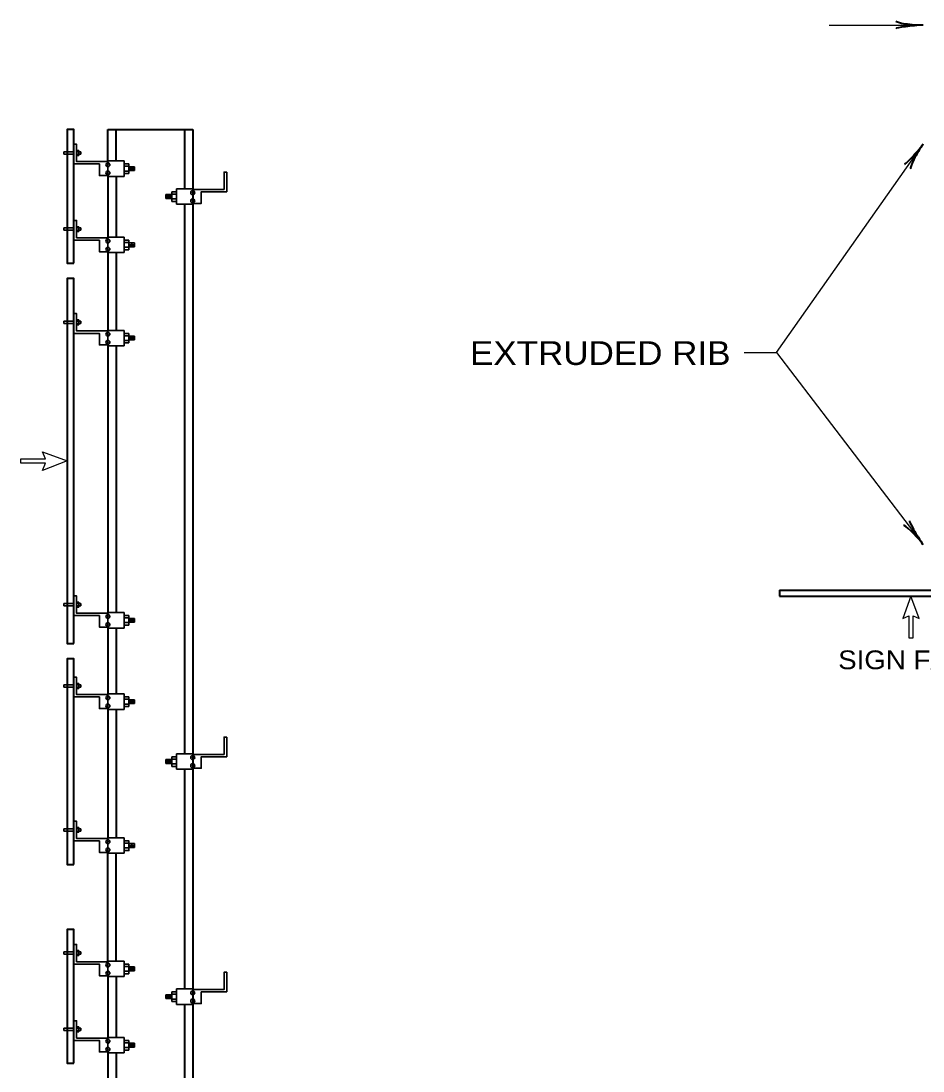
# Model space of a CAD drawing. Extents: x 851 to 1706, y -23 to 521.
# Drawn here: x 1360 to 1475.1, y 110.6 to 244.7 of the extents above; entities that cross this region are included whole.
import ezdxf
from ezdxf.enums import TextEntityAlignment as Align

# ---------------------------------------------------------------- set-up
doc = ezdxf.new("R2010")
doc.units = 0
doc.header["$PDMODE"] = 32
doc.header["$PDSIZE"] = 0.5
doc.layers.add('1', color=7, linetype='Continuous', lineweight=35)

msp = doc.modelspace()

# ---------------------------------------------------------------- linework, layer by layer
at = {"layer": '1', "lineweight": 25}
for p, q in [((1463.149, 244.147), (1475.115, 244.147)), ((1456.404, 202.356), (1475.115, 177.854)), ((1386.238, 153.264), (1385.844, 153.264)), ((1386.238, 153.264), (1386.238, 150.749))]:
    msp.add_line(p, q, dxfattribs=at)
at = {"layer": '1', "lineweight": 40}
for p, q in [((1371.049, 230.821), (1381.875, 230.821)), ((1371.049, 226.802), (1371.049, 230.821)), ((1371.049, 230.821), (1381.875, 230.821)), ((1372.082, 226.802), (1372.082, 230.821)), ((1380.841, 230.821), (1380.841, 223.248)), ((1381.875, 230.821), (1381.875, 128.673)), ((1371.049, 224.834), (1371.049, 217.07)), ((1372.082, 224.834), (1372.082, 217.07)), ((1380.841, 221.28), (1380.841, 151.132)), ((1371.049, 215.102), (1371.049, 205.178)), ((1372.082, 215.102), (1372.082, 205.178)), ((1371.049, 203.21), (1371.049, 169.147)), ((1372.082, 203.21), (1372.082, 169.147)), ((1456.789, 172.002), (1540.733, 172.002)), ((1456.789, 172.002), (1456.789, 171.233)), ((1456.789, 171.233), (1540.733, 171.233)), ((1371.049, 167.179), (1371.049, 158.759)), ((1372.082, 167.179), (1372.082, 158.759)), ((1371.049, 156.791), (1371.049, 140.388)), ((1372.082, 156.791), (1372.082, 140.388)), ((1380.841, 149.163), (1380.841, 128.673)), ((1371.049, 128.673), (1371.049, 138.42)), ((1372.082, 128.673), (1372.082, 138.42)), ((1371.049, 124.654), (1371.049, 128.673)), ((1372.082, 124.654), (1372.082, 128.673)), ((1380.841, 128.673), (1380.841, 121.1)), ((1381.875, 128.673), (1381.875, 21.729)), ((1371.049, 122.686), (1371.049, 114.922)), ((1372.082, 122.686), (1372.082, 114.922)), ((1380.841, 119.132), (1380.841, 48.984)), ((1371.049, 112.954), (1371.049, 103.03)), ((1372.082, 112.954), (1372.082, 103.03))]:
    msp.add_line(p, q, dxfattribs=at)
at = {"layer": '1'}
for p, q in [((1365.425, 227.978), (1365.425, 227.677)), ((1366.686, 227.978), (1365.425, 227.978)), ((1366.686, 228.934), (1366.686, 226.419)), ((1367.342, 228.142), (1367.047, 228.142)), ((1367.604, 227.978), (1367.047, 227.978)), ((1367.342, 228.142), (1367.342, 227.513)), ((1367.604, 227.978), (1367.604, 227.677)), ((1366.686, 227.677), (1365.425, 227.677)), ((1367.604, 227.677), (1367.047, 227.677)), ((1367.342, 227.513), (1367.047, 227.513)), ((1371.049, 226.802), (1373.116, 226.802)), ((1371.049, 226.119), (1371.049, 226.802)), ((1373.116, 226.802), (1373.116, 224.834)), ((1371.049, 226.119), (1371.049, 225.517)), ((1371.049, 225.08), (1371.049, 225.517)), ((1373.116, 226.419), (1373.726, 226.419)), ((1373.116, 226.119), (1373.726, 226.119)), ((1373.116, 225.517), (1373.726, 225.517)), ((1373.116, 225.189), (1373.726, 225.189)), ((1373.726, 226.419), (1373.726, 225.189)), ((1373.726, 226.064), (1374.461, 226.064)), ((1373.726, 225.572), (1374.461, 225.572)), ((1373.918, 225.927), (1373.918, 225.681)), ((1374.097, 226.064), (1374.097, 225.572)), ((1374.297, 225.927), (1374.297, 225.681)), ((1374.461, 226.064), (1374.461, 225.572)), ((1386.238, 225.381), (1386.238, 222.865)), ((1371.049, 225.08), (1371.049, 224.834)), ((1371.049, 224.834), (1373.116, 224.834)), ((1379.197, 222.51), (1378.463, 222.51)), ((1378.463, 222.51), (1378.463, 222.018)), ((1378.827, 222.51), (1378.827, 222.018)), ((1379.808, 222.865), (1379.197, 222.865)), ((1379.197, 222.865), (1379.197, 221.635)), ((1379.808, 222.565), (1379.197, 222.565)), ((1381.875, 223.248), (1379.808, 223.248)), ((1379.808, 223.248), (1379.808, 221.28)), ((1381.875, 222.565), (1381.875, 223.248)), ((1381.875, 222.565), (1381.875, 221.963)), ((1379.197, 222.018), (1378.463, 222.018)), ((1378.627, 222.373), (1378.627, 222.127)), ((1379.005, 222.373), (1379.005, 222.127)), ((1379.808, 221.963), (1379.197, 221.963)), ((1379.808, 221.635), (1379.197, 221.635)), ((1381.875, 221.28), (1379.808, 221.28)), ((1381.875, 221.526), (1381.875, 221.963)), ((1381.875, 221.526), (1381.875, 221.28)), ((1366.686, 219.202), (1366.686, 216.687)), ((1365.425, 218.245), (1365.425, 217.945)), ((1366.686, 218.245), (1365.425, 218.245)), ((1366.686, 217.945), (1365.425, 217.945)), ((1367.342, 218.41), (1367.047, 218.41)), ((1367.604, 218.245), (1367.047, 218.245)), ((1367.604, 217.945), (1367.047, 217.945)), ((1367.342, 217.781), (1367.047, 217.781)), ((1367.342, 218.41), (1367.342, 217.781)), ((1367.604, 218.245), (1367.604, 217.945)), ((1371.049, 217.07), (1373.116, 217.07)), ((1371.049, 216.387), (1371.049, 217.07)), ((1371.049, 216.387), (1371.049, 215.785)), ((1373.116, 217.07), (1373.116, 215.102)), ((1373.116, 216.687), (1373.726, 216.687)), ((1373.116, 216.387), (1373.726, 216.387)), ((1373.726, 216.687), (1373.726, 215.457)), ((1373.726, 216.332), (1374.461, 216.332)), ((1373.726, 215.84), (1374.461, 215.84)), ((1373.918, 216.195), (1373.918, 215.949)), ((1374.097, 216.332), (1374.097, 215.84)), ((1374.297, 216.195), (1374.297, 215.949)), ((1374.461, 216.332), (1374.461, 215.84)), ((1371.049, 215.348), (1371.049, 215.785)), ((1371.049, 215.348), (1371.049, 215.102)), ((1371.049, 215.102), (1373.116, 215.102)), ((1373.116, 215.785), (1373.726, 215.785)), ((1373.116, 215.457), (1373.726, 215.457)), ((1366.686, 207.31), (1366.686, 204.795)), ((1367.342, 206.518), (1367.047, 206.518)), ((1367.342, 206.518), (1367.342, 205.889)), ((1365.425, 206.354), (1365.425, 206.053)), ((1366.686, 206.354), (1365.425, 206.354)), ((1366.686, 206.053), (1365.425, 206.053)), ((1367.604, 206.354), (1367.047, 206.354)), ((1367.604, 206.053), (1367.047, 206.053)), ((1367.342, 205.889), (1367.047, 205.889)), ((1367.604, 206.354), (1367.604, 206.053)), ((1371.049, 205.178), (1373.116, 205.178)), ((1371.049, 204.495), (1371.049, 205.178)), ((1373.116, 205.178), (1373.116, 203.21)), ((1371.049, 204.495), (1371.049, 203.893)), ((1371.049, 203.456), (1371.049, 203.893)), ((1373.116, 204.795), (1373.726, 204.795)), ((1373.116, 204.495), (1373.726, 204.495)), ((1373.116, 203.893), (1373.726, 203.893)), ((1373.726, 204.795), (1373.726, 203.565)), ((1373.726, 204.44), (1374.461, 204.44)), ((1373.726, 203.948), (1374.461, 203.948)), ((1373.918, 204.303), (1373.918, 204.057)), ((1374.097, 204.44), (1374.097, 203.948)), ((1374.297, 204.303), (1374.297, 204.057)), ((1374.461, 204.44), (1374.461, 203.948)), ((1371.049, 203.456), (1371.049, 203.21)), ((1371.049, 203.21), (1373.116, 203.21)), ((1373.116, 203.565), (1373.726, 203.565)), ((1365.425, 170.323), (1365.425, 170.022)), ((1366.686, 170.323), (1365.425, 170.323)), ((1366.686, 171.28), (1366.686, 168.765)), ((1367.342, 170.487), (1367.047, 170.487)), ((1367.604, 170.323), (1367.047, 170.323)), ((1367.342, 170.487), (1367.342, 169.858)), ((1367.604, 170.323), (1367.604, 170.022)), ((1366.686, 170.022), (1365.425, 170.022)), ((1367.604, 170.022), (1367.047, 170.022)), ((1367.342, 169.858), (1367.047, 169.858)), ((1371.049, 169.147), (1373.116, 169.147)), ((1371.049, 168.464), (1371.049, 169.147)), ((1373.116, 169.147), (1373.116, 167.179)), ((1371.049, 168.464), (1371.049, 167.863)), ((1371.049, 167.425), (1371.049, 167.863)), ((1373.116, 168.765), (1373.726, 168.765)), ((1373.116, 168.464), (1373.726, 168.464)), ((1373.116, 167.863), (1373.726, 167.863)), ((1373.726, 168.765), (1373.726, 167.534)), ((1373.726, 168.409), (1374.461, 168.409)), ((1373.726, 167.917), (1374.461, 167.917)), ((1373.918, 168.273), (1373.918, 168.026)), ((1374.097, 168.409), (1374.097, 167.917)), ((1374.297, 168.273), (1374.297, 168.026)), ((1374.461, 168.409), (1374.461, 167.917)), ((1371.049, 167.425), (1371.049, 167.179)), ((1371.049, 167.179), (1373.116, 167.179)), ((1373.116, 167.534), (1373.726, 167.534)), ((1366.686, 160.891), (1366.686, 158.376)), ((1365.425, 159.935), (1365.425, 159.634)), ((1366.686, 159.935), (1365.425, 159.935)), ((1366.686, 159.634), (1365.425, 159.634)), ((1367.342, 160.099), (1367.047, 160.099)), ((1367.604, 159.935), (1367.047, 159.935)), ((1367.604, 159.634), (1367.047, 159.634)), ((1367.342, 160.099), (1367.342, 159.47)), ((1367.604, 159.935), (1367.604, 159.634)), ((1367.342, 159.47), (1367.047, 159.47)), ((1371.049, 158.759), (1373.116, 158.759)), ((1371.049, 158.076), (1371.049, 158.759)), ((1373.116, 158.759), (1373.116, 156.791)), ((1373.116, 158.376), (1373.726, 158.376)), ((1373.726, 158.376), (1373.726, 157.146)), ((1371.049, 158.076), (1371.049, 157.474)), ((1371.049, 157.037), (1371.049, 157.474)), ((1371.049, 157.037), (1371.049, 156.791)), ((1373.116, 158.076), (1373.726, 158.076)), ((1373.116, 157.474), (1373.726, 157.474)), ((1373.116, 157.146), (1373.726, 157.146)), ((1373.726, 158.021), (1374.461, 158.021)), ((1373.726, 157.529), (1374.461, 157.529)), ((1373.918, 157.884), (1373.918, 157.638)), ((1374.097, 158.021), (1374.097, 157.529)), ((1374.297, 157.884), (1374.297, 157.638)), ((1374.461, 158.021), (1374.461, 157.529)), ((1371.049, 156.791), (1373.116, 156.791)), ((1386.238, 153.264), (1386.238, 150.749)), ((1379.197, 150.394), (1378.463, 150.394)), ((1378.463, 150.394), (1378.463, 149.902)), ((1378.627, 150.257), (1378.627, 150.011)), ((1378.827, 150.394), (1378.827, 149.902)), ((1379.005, 150.257), (1379.005, 150.011)), ((1379.808, 150.749), (1379.197, 150.749)), ((1379.197, 150.749), (1379.197, 149.519)), ((1379.808, 150.448), (1379.197, 150.448)), ((1381.875, 151.132), (1379.808, 151.132)), ((1379.808, 151.132), (1379.808, 149.163)), ((1381.875, 150.448), (1381.875, 151.132)), ((1381.875, 150.448), (1381.875, 149.847)), ((1379.197, 149.902), (1378.463, 149.902)), ((1379.808, 149.847), (1379.197, 149.847)), ((1379.808, 149.519), (1379.197, 149.519)), ((1381.875, 149.163), (1379.808, 149.163)), ((1381.875, 149.41), (1381.875, 149.847)), ((1381.875, 149.41), (1381.875, 149.163)), ((1366.686, 142.52), (1366.686, 140.006)), ((1365.425, 141.564), (1365.425, 141.263)), ((1366.686, 141.564), (1365.425, 141.564)), ((1366.686, 141.263), (1365.425, 141.263)), ((1367.342, 141.728), (1367.047, 141.728)), ((1367.604, 141.564), (1367.047, 141.564)), ((1367.604, 141.263), (1367.047, 141.263)), ((1367.342, 141.099), (1367.047, 141.099)), ((1367.342, 141.728), (1367.342, 141.099)), ((1367.604, 141.564), (1367.604, 141.263)), ((1371.049, 140.388), (1373.116, 140.388)), ((1371.049, 139.705), (1371.049, 140.388)), ((1371.049, 139.705), (1371.049, 139.103)), ((1373.116, 140.388), (1373.116, 138.42)), ((1373.116, 139.705), (1373.726, 139.705)), ((1373.726, 139.65), (1374.461, 139.65)), ((1373.918, 139.513), (1373.918, 139.267)), ((1374.097, 139.65), (1374.097, 139.158)), ((1374.297, 139.513), (1374.297, 139.267)), ((1374.461, 139.65), (1374.461, 139.158)), ((1371.049, 138.666), (1371.049, 139.103)), ((1371.049, 138.666), (1371.049, 138.42)), ((1371.049, 138.42), (1373.116, 138.42)), ((1373.116, 139.103), (1373.726, 139.103)), ((1373.726, 139.158), (1374.461, 139.158)), ((1366.686, 126.787), (1366.686, 124.272)), ((1367.342, 125.994), (1367.047, 125.994)), ((1367.342, 125.994), (1367.342, 125.365)), ((1365.425, 125.83), (1365.425, 125.529)), ((1366.686, 125.83), (1365.425, 125.83)), ((1366.686, 125.529), (1365.425, 125.529)), ((1367.604, 125.83), (1367.047, 125.83)), ((1367.604, 125.529), (1367.047, 125.529)), ((1367.342, 125.365), (1367.047, 125.365)), ((1367.604, 125.83), (1367.604, 125.529)), ((1371.049, 124.654), (1373.116, 124.654)), ((1371.049, 123.971), (1371.049, 124.654)), ((1373.116, 124.654), (1373.116, 122.686)), ((1371.049, 123.971), (1371.049, 123.37)), ((1371.049, 122.932), (1371.049, 123.37)), ((1373.116, 124.272), (1373.726, 124.272)), ((1373.116, 123.971), (1373.726, 123.971)), ((1373.116, 123.37), (1373.726, 123.37)), ((1373.726, 124.272), (1373.726, 123.041)), ((1373.726, 123.916), (1374.461, 123.916)), ((1373.726, 123.424), (1374.461, 123.424)), ((1373.918, 123.78), (1373.918, 123.534)), ((1374.097, 123.916), (1374.097, 123.424)), ((1374.297, 123.78), (1374.297, 123.534)), ((1374.461, 123.916), (1374.461, 123.424)), ((1371.049, 122.932), (1371.049, 122.686)), ((1371.049, 122.686), (1373.116, 122.686)), ((1373.116, 123.041), (1373.726, 123.041)), ((1386.238, 123.233), (1386.238, 120.718)), ((1379.808, 120.718), (1379.197, 120.718)), ((1379.197, 120.718), (1379.197, 119.488)), ((1381.875, 121.101), (1379.808, 121.101)), ((1379.808, 121.101), (1379.808, 119.132)), ((1381.875, 120.417), (1381.875, 121.101)), ((1379.197, 120.362), (1378.463, 120.362)), ((1378.463, 120.362), (1378.463, 119.87)), ((1379.197, 119.87), (1378.463, 119.87)), ((1378.627, 120.226), (1378.627, 119.98)), ((1378.827, 120.362), (1378.827, 119.87)), ((1379.005, 120.226), (1379.005, 119.98)), ((1379.808, 120.417), (1379.197, 120.417)), ((1379.808, 119.816), (1379.197, 119.816)), ((1379.808, 119.488), (1379.197, 119.488)), ((1381.875, 120.417), (1381.875, 119.816)), ((1381.875, 119.378), (1381.875, 119.816)), ((1381.875, 119.378), (1381.875, 119.132)), ((1381.875, 119.132), (1379.808, 119.132)), ((1366.686, 117.055), (1366.686, 114.54)), ((1365.425, 116.098), (1365.425, 115.797)), ((1366.686, 116.098), (1365.425, 116.098)), ((1366.686, 115.797), (1365.425, 115.797)), ((1367.342, 116.262), (1367.047, 116.262)), ((1367.604, 116.098), (1367.047, 116.098)), ((1367.604, 115.797), (1367.047, 115.797)), ((1367.342, 115.633), (1367.047, 115.633)), ((1367.342, 116.262), (1367.342, 115.633)), ((1367.604, 116.098), (1367.604, 115.797)), ((1371.049, 114.922), (1373.116, 114.922)), ((1371.049, 114.239), (1371.049, 114.922)), ((1371.049, 114.239), (1371.049, 113.637)), ((1373.116, 114.922), (1373.116, 112.954)), ((1373.116, 114.54), (1373.726, 114.54)), ((1373.116, 114.239), (1373.726, 114.239)), ((1373.726, 114.54), (1373.726, 113.309)), ((1373.726, 114.184), (1374.461, 114.184)), ((1373.918, 114.047), (1373.918, 113.801)), ((1374.097, 114.184), (1374.097, 113.692)), ((1374.297, 114.047), (1374.297, 113.801)), ((1374.461, 114.184), (1374.461, 113.692)), ((1371.049, 113.2), (1371.049, 113.637)), ((1371.049, 113.2), (1371.049, 112.954)), ((1371.049, 112.954), (1373.116, 112.954)), ((1373.116, 113.637), (1373.726, 113.637)), ((1373.116, 113.309), (1373.726, 113.309)), ((1373.726, 113.692), (1374.461, 113.692))]:
    msp.add_line(p, q, dxfattribs=at)
at = {"layer": '1', "lineweight": 40}
for points in [[(1366.686, 213.762), (1366.686, 230.821), (1365.856, 230.821), (1365.856, 213.762)], [(1366.686, 165.211), (1366.686, 211.794), (1365.856, 211.794), (1365.856, 165.211)], [(1366.686, 136.998), (1366.686, 163.242), (1365.856, 163.242), (1365.856, 136.998)], [(1366.686, 111.614), (1366.686, 128.673), (1365.856, 128.673), (1365.856, 111.614)]]:
    msp.add_lwpolyline(points, close=True, dxfattribs=at)
at = {"layer": '1', "lineweight": 25}
for points in [[(1366.686, 228.934), (1367.047, 228.934), (1367.047, 226.72)], [(1452.266, 202.356), (1456.404, 202.356), (1475.115, 228.93)], [(1366.686, 219.202), (1367.047, 219.202), (1367.047, 216.988)], [(1366.686, 207.31), (1367.047, 207.31), (1367.047, 205.096)], [(1366.686, 171.28), (1367.047, 171.28), (1367.047, 169.065)], [(1366.686, 160.891), (1367.047, 160.891), (1367.047, 158.677)], [(1366.686, 160.891), (1367.047, 160.891), (1367.047, 158.677)], [(1366.686, 142.52), (1367.047, 142.52), (1367.047, 140.306)], [(1366.686, 126.787), (1367.047, 126.787), (1367.047, 124.572)], [(1366.686, 117.055), (1367.047, 117.055), (1367.047, 114.84)]]:
    msp.add_lwpolyline(points, dxfattribs=at)
at = {"layer": '1'}
for points in [[(1366.686, 228.934), (1367.047, 228.934), (1367.047, 226.72), (1371.049, 226.72)], [(1371.049, 224.943), (1369.966, 224.943), (1369.966, 226.419), (1366.686, 226.419)], [(1386.238, 225.381), (1385.877, 225.381), (1385.877, 223.166), (1381.875, 223.166)], [(1381.875, 221.389), (1382.957, 221.389), (1382.957, 222.865), (1386.238, 222.865)], [(1366.686, 219.202), (1367.047, 219.202), (1367.047, 216.988), (1371.049, 216.988)], [(1371.049, 215.211), (1369.966, 215.211), (1369.966, 216.687), (1366.686, 216.687)], [(1366.686, 207.31), (1367.047, 207.31), (1367.047, 205.096), (1371.049, 205.096)], [(1371.049, 203.319), (1369.966, 203.319), (1369.966, 204.795), (1366.686, 204.795)], [(1366.686, 171.28), (1367.047, 171.28), (1367.047, 169.065), (1371.049, 169.065)], [(1371.049, 167.288), (1369.966, 167.288), (1369.966, 168.765), (1366.686, 168.765)], [(1366.686, 160.891), (1367.047, 160.891), (1367.047, 158.677), (1371.049, 158.677)], [(1371.049, 156.9), (1369.966, 156.9), (1369.966, 158.376), (1366.686, 158.376)], [(1386.238, 153.264), (1385.877, 153.264), (1385.877, 151.05), (1381.875, 151.05)], [(1381.875, 149.273), (1382.957, 149.273), (1382.957, 150.749), (1386.238, 150.749)], [(1366.686, 142.52), (1367.047, 142.52), (1367.047, 140.306), (1371.049, 140.306)], [(1371.049, 138.529), (1369.966, 138.529), (1369.966, 140.006), (1366.686, 140.006)], [(1373.116, 140.006), (1373.726, 140.006), (1373.726, 138.775), (1373.116, 138.775)], [(1366.686, 126.787), (1367.047, 126.787), (1367.047, 124.572), (1371.049, 124.572)], [(1371.049, 122.795), (1369.966, 122.795), (1369.966, 124.272), (1366.686, 124.272)], [(1386.238, 123.233), (1385.877, 123.233), (1385.877, 121.019), (1381.875, 121.019)], [(1381.875, 119.242), (1382.957, 119.242), (1382.957, 120.718), (1386.238, 120.718)], [(1366.686, 117.055), (1367.047, 117.055), (1367.047, 114.84), (1371.049, 114.84)], [(1371.049, 113.063), (1369.966, 113.063), (1369.966, 114.54), (1366.686, 114.54)]]:
    msp.add_lwpolyline(points, dxfattribs=at)
at = {"layer": '1', "lineweight": 25}
for points in [[(1363.068, 188.202), (1359.951, 188.202), (1359.951, 188.776), (1363.068, 188.776), (1362.712, 189.678), (1365.856, 188.502), (1362.712, 187.299)], [(1363.068, 188.202), (1359.951, 188.202), (1359.951, 188.776), (1363.068, 188.776), (1362.712, 189.678), (1365.856, 188.502), (1362.712, 187.299)], [(1473.578, 171.233), (1472.519, 168.401), (1473.307, 168.721), (1473.307, 165.913), (1473.849, 165.913), (1473.849, 168.721), (1474.637, 168.401)]]:
    msp.add_lwpolyline(points, close=True, dxfattribs=at)
at = {"layer": '1', "lineweight": 40}
for centre, major_axis, ratio, start_param, end_param in [((1473.805, 244.478), (2.143, -0.187), 0.122415, 3.1415927, 5.386832), ((1473.77, 243.893), (2.108, 0.211), 0.07063, 0.8650754, 3.1424706), ((1474.133, 227.977), (1.386, 1.602), 0.07063, 3.1407148, 5.41811), ((1474.632, 227.669), (1.08, 1.86), 0.122415, 0.8963533, 3.1415927), ((1474.056, 178.694), (1.449, -1.589), 0.122415, 0.8963533, 3.1415927), ((1474.5, 179.077), (1.112, -1.803), 0.07063, 3.1407148, 5.41811)]:
    msp.add_ellipse(centre, major_axis=major_axis, ratio=ratio, start_param=start_param, end_param=end_param, dxfattribs=at)
at = {"layer": '1'}
for p in [(1371.049, 226.31), (1371.049, 225.271), (1381.875, 222.756), (1381.875, 221.717), (1371.049, 216.578), (1371.049, 215.539), (1371.049, 204.686), (1371.049, 203.647), (1371.049, 168.655), (1371.049, 167.616), (1371.049, 158.267), (1371.049, 157.228), (1381.875, 150.64), (1381.875, 149.601), (1371.049, 139.896), (1371.049, 138.857), (1371.049, 124.162), (1371.049, 123.123), (1381.875, 120.608), (1381.875, 119.57), (1371.049, 114.43), (1371.049, 113.391)]:
    msp.add_point(p, dxfattribs=at)

# ---------------------------------------------------------------- texts
at = {"layer": '1', "width": 1.1}
for s, height, p in [('EXTRUDED RIB', 3.037, (1433.91, 200.756)), ('SIGN FACE', 2.4, (1473.8, 161.917))]:
    msp.add_text(s, height=height, dxfattribs=at).set_placement(p, align=Align.CENTER)

doc.saveas('drawing.dxf')
